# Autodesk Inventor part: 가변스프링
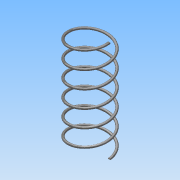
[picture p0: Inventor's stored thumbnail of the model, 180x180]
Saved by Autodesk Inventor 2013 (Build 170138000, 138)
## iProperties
Created: 2016-11
Part Number: 가변스프링
Material: 강철, 탄소
Document SubType Name: Modeling
Designer: Administrator
Mass: 14.8357 g
Surface Area: 38.0676 cm^2
Volume: 1.8851 cm^3
Density: 7.87 g/cm^3
Author: Administrator
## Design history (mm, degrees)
sketch "스케치1"
  geometry: L1 (0, 0)-(16, 0); L2 (16, 0)-(16, 84.368); L3 (16, 84.368)-(0, 84.368); L4 (0, 84.368)-(0, 0); C1 r 1 at (16, 0)
  constraints: 8 end point, 2 parallel, 1 centre point, 1 coincident, 1 horizontal, 1 perpendicular
  dimensions: "d0" = 32 diameter of L2 L4; "d2" = 84.36759 distance of L1.end L2.end (derived); "d3" = 2 diameter of C1
feature "코일1" sketch "스케치1" pitch "d4" = 10; turns "d6" = 6; dims "d5" = 84.36759 (= d2), "d7" = 0, angle "d8" = 90 deg, angle "d9" = 90 deg, "d10" = 0, "d11" = 0
node "작업 평면1"
feature "분할1"
feature "분할2"
node "솔리드1"
other parameters: "d12" = 85
